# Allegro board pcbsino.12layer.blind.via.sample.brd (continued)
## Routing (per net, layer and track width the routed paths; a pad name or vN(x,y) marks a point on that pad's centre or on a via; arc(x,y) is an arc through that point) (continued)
ETH0_DVDD10: length 6.1
  INT_L3 w0.254: v3(49.22,34.07) 49.42,34.28 v2(49.93,34.28)
  SIG_L10 w0.254: v5(49.72,34.18) 49.7,34.2 49.34,34.2 v3(49.22,34.07)
  BOTTOM w0.114: 49.98,34.68 C195.1 50.11,34.33 ; 50,34.45 v5(49.72,34.18)
  BOTTOM w0.381: 50.11,34.33 49.98,34.45 49.98,34.61 ; 49.98,34.61 49.95,34.64 49.86,34.55 49.5,34.55 49.04,35.01 48.33,35.01 L15.1 ; 49.98,34.61 49.98,34.68 49.68,34.98 49.68,35.75 C194.1 ; C195.1 50,34.45
ETH0_DVDD33: length 40.9
  TOP w0.114: 43.64,35.12 44.86,35.12
  TOP w0.254: R288.2 44.96,35.21 44.86,35.12 ; R276.1 53.05,37.89 52.82,37.89 52.81,37.91 52.7,37.91 52.31,38.29 49.52,38.29 v2(49.32,38.09) ; R277.1 46.97,28.58 R284.2 ; U17.29 47.25,32.09 47,31.84 C181.1 v2(47.01,31.61) 47.72,31.61 47.8,31.69 U17.30 ; 43.64,35.12 v2(43.35,35.12) 43.35,35.45 43.32,35.48 R279.2
  INT_L3 w0.254: 46.98,31.59 v2(47.01,31.61) ; 46.98,31.59 46.98,33.09 48.07,34.18 v3(48.51,34.18) ; 46.98,31.59 46.98,31.23 46.58,30.82 46.58,29.81 v2(46.98,29.4) ; v2(43.35,35.12) 43.37,35.09 v3(43.37,34.63) 43.37,34.58 43.4,34.56 v2(43.4,33.87) ; v3(49.18,37.71) 49.19,37.71 49.19,37.73 49.22,37.76 49.22,37.99 v2(49.32,38.09)
  SIG_L10 w0.254: v5(43.37,34.15) v3(43.37,34.63) ; v5(48.63,37.94) 48.84,37.73 49.16,37.73 v3(49.18,37.71)
  SIG_L10 w0.381: v3(48.51,34.18) 48.56,34.23 48.56,35.53 v4(48.72,35.7)
  GND_L11 w0.381: v5(48.87,36.07) v4(48.72,35.7)
  BOTTOM w0.254: v5(48.63,37.94) 48.48,37.78 C183.1 ; 46.24,36.5 45.89,36.84 44.34,36.84 43.37,35.88 v5(43.37,34.15) 43.25,34.15 42.54,33.44 42.54,31.13 41.9,30.49 41.11,30.49 R259.2
  BOTTOM w0.381: v5(48.87,36.07) 47.35,36.07 47.08,36.34 C182.1 46.24,36.39 C183.1 46.19,37.83 L11.1
ETH0_INTN: length 51.7
  TOP w0.114: U17.34 47.18,30.09 R277.2
  INT_L3 w0.091: v3(48.53,29.6) 47.69,29.6 v2(47.03,30.26) ; v3(31.69,19.32) 31.49,19.11 v2(31.49,18.76)
  SIG_L10 w0.091: v3(48.53,29.6) 48.51,29.58 48.51,28.18 50.51,26.18 50.51,20.08 50.97,19.62 50.97,19.2 50.76,18.99 50.54,18.99 48.3,16.75 46.68,16.75 46.14,16.22 46.14,13.96 45.59,13.4 45.59,10.42 46.5,9.51 46.5,9.03 45.9,8.44 39.05,8.44 36.2,11.29 35.23,11.29 34.05,12.47 33.58,12.47 32.02,14.03 32.02,16.58 31.69,16.91 v3(31.69,19.32)
ETH0_LED0/PHYAD0: length 4.1
  TOP w0.114: R283.2 47.49,27.12 R284.1 47,27.62 47.44,28.06 47.44,29.3 47.83,29.69 U17.35
ETH0_RESETN: length 21.4
  TOP w0.114: v2(39.94,31.23) 39.49,30.78 39.47,30.78 U6.U3 ; v2(41.85,39.56) 42.16,39.56 42.21,39.51 46.96,39.51 49.64,42.2 R275.2 50.08,42.59 U18.1
  INT_L3 w0.091: v2(41.85,39.56) 41.57,39.84 v3(41.44,39.84) ; v2(39.94,31.23) 40.02,31.31 v3(40.58,31.31)
  SIG_L10 w0.091: v3(40.58,31.31) 40.54,31.35 40.54,36.09 41.09,36.65 41.09,39.57 41.36,39.84 v3(41.44,39.84)
ETH0_RSET: length 1.7
  TOP w0.114: U17.48 53.53,28.09 53.84,27.78 54.33,27.78 R272.2
ETH0_VDD10: length 12.7
  SIG_L10 w0.381: v5(50.08,29.22) 49.5,29.81 49.5,32.4 48.86,33.03 v5(48.86,33.26)
  BOTTOM w0.114: C186.1 49.88,29.43 v5(50.08,29.22)
  BOTTOM w0.254: v5(50.08,29.22) 50.12,29.18 C187.1
  BOTTOM w0.381: v5(48.86,33.26) 48.43,33.69 L15.2 ; 50.1,29.21 48.78,29.21 48.61,29.38 48.61,28.11 L14.2 47.48,28.73 L13.2
ETH0_VDDREG33: length 5.6
  TOP w0.114: v2(48.07,31.29) U17.31
  INT_L3 w0.254: v3(48.68,31.59) 48.37,31.59 v2(48.07,31.29)
  SIG_L10 w0.254: v3(48.68,31.59) 48.63,31.59 47.91,32.31 v5(47.86,32.31)
  BOTTOM w0.254: C184.1 47.78,32.37 47.79,32.37 v5(47.86,32.31)
  BOTTOM w0.381: C184.1 46.93,32.4 C185.1 46.7,32.97 L12.1
ETH0_XTAL_IN: length 5.5
  TOP w0.114: Y4.3 51.06,23.92 51.96,24.82 51.96,26.61 51.58,26.98 C188.1 52.33,27.82 U17.45
ETH0_XTAL_OUT: length 4.9
  TOP w0.114: Y4.1 53.09,25.52 52.54,24.98 52.38,24.98 52.26,25.09 52.26,26.83 C191.1 52.53,27.41 52.73,27.6 U17.46
ETH1_AND_RESETN: length 4.3
  TOP w0.114: U20.4 53.76,18.89 53.94,18.71 53.94,17.7 R305.2 53.78,17.54 51.96,17.54 51.69,17.27 U19.13
ETH1_AVDD10: length 16.8
  TOP w0.114: 51.29,10.74 51.3,10.73 v2(51.3,10.71)
  TOP w0.254: v2(51.3,10.71) 51.29,10.72 U19.47 ; U19.9 v2(53.1,14.96) ; U19.4 v2(53.15,12.96)
  INT_L3 w0.254: v2(53.1,14.96) 52.71,14.57 v3(52.52,14.57) 52.47,14.52 52.47,13.64 v2(53.15,12.96) ; v2(51.3,10.71) 51.33,10.68 51.33,10.3 v3(51.25,10.22)
  SIG_L10 w0.254: v5(51.73,10.27) 51.71,10.25 51.27,10.25 v3(51.25,10.22) ; v5(52.65,13.86) 52.52,13.98 v3(52.52,14.57)
  BOTTOM w0.381: C211.1 52.64,12.98 C210.1 52.64,12.65 51.67,11.69 C212.1 51.67,10.33 v5(51.73,10.27) 51.66,10.2 51.66,9.23 50.91,8.49 C213.1 47.63,8.13 L20.1
ETH1_AVDD33: length 14.3
  TOP w0.254: v2(53.04,11.7) 52.98,11.76 U19.1 ; U19.12 v2(53.12,16.16)
  INT_L3 w0.254: v2(53.12,16.16) 52.39,15.43 v3(52.39,15.28)
  INT_L3 w0.381: v2(53.04,11.7) 53.1,11.63 v3(53.1,11.27)
  SIG_L10 w0.254: v5(52.39,15.66) v3(52.39,15.28)
  SIG_L10 w0.381: v5(53.1,11.77) v3(53.1,11.27)
  BOTTOM w0.114: 53.06,11.77 v5(53.1,11.77)
  BOTTOM w0.254: v5(52.39,15.66) 52.4,15.65 52.4,15.63
  BOTTOM w0.381: L16.1 50,16.95 C200.1 50.56,17 52.4,17 52.67,16.73 C199.1 52.67,15.9 52.4,15.63 53.31,14.72 53.31,12.02 C198.1
ETH1_DVDD10: length 6.7
  TOP w0.114: C214.1 48.09,18.15 U19.22
  TOP w0.254: C214.1 48.03,18.33 49,19.29 v2(49.01,19.29)
  INT_L3 w0.254: v3(49.34,18.81) 49.01,19.14 v2(49.01,19.29)
  SIG_L10 w0.254: v3(49.34,18.81) 49.34,18.76 v5(48.35,17.77)
  BOTTOM w0.381: L21.1 48.18,18.17 C215.1
ETH1_DVDD33: length 34.2
  TOP w0.203: 44.28,8.33 44.28,8.37 R306.1 ; 44.28,8.33 R313.2 ; 44.28,8.33 v2(43.93,8.67) ; U19.29 46.08,14.56 45.61,14.08 v7(45.61,14.03) 45.73,14.16 U19.30
  TOP w0.254: R305.1 54.77,17.19 54.52,16.93 v2(52.39,16.93) ; R317.2 43.3,12.28 v2(43.32,12.26) ; R308.2 42.76,14.28 v2(42.49,14.01)
  INT_L3 w0.203: v2(43.32,12.26) 44.64,10.94 44.64,9.39 v2(43.93,8.67)
  INT_L3 w0.254: v2(43.32,12.26) 43.4,12.33 44.34,12.33 45.61,13.6 v7(45.61,14.03) 45.64,14.06 45.64,14.69 46.45,15.51 50.72,15.51 52.14,16.93 v2(52.39,16.93) ; v2(41.62,12.79) 41.85,12.79 v3(42.1,13.04) 42.49,13.42 v2(42.49,14.01)
  SIG_L10 w0.254: v7(45.61,14.03) 44.62,13.04 v3(42.1,13.04)
  BOTTOM w0.381: L17.1 44.92,16.39 C203.1 44.99,16.1 C201.1 C202.1 45.69,14.12 v7(45.61,14.03)
ETH1_INTN: length 22.2
  TOP w0.114: v2(44.26,9.77) 44.33,9.7 R306.2 45.64,10.68 45.64,12.28 45.91,12.56 U19.34
  TOP w0.12: v8(32.68,17.58) U6.A11
  INT_L3 w0.091: v2(44.26,9.77) 43.88,9.39 43.83,9.39 v3(43.81,9.36)
  SIG_L10 w0.091: v3(43.81,9.36) 41.87,9.36 37.48,13.75 33.73,13.75 32.68,14.81 32.68,16.85 32.68,16.85 v8(32.68,17.58)
ETH1_LED0/PHYAD0: length 5.5
  TOP w0.114: U19.35 46,12.16 45.89,12.04 45.89,10.04 45.66,9.81 45.66,8.65 45.44,8.43 R312.2 45.2,7.66 R313.1
ETH1_RESETN: length 25.6
  TOP w0.114: U20.1 50.9,21 R304.2
  INT_L3 w0.091: v2(50.61,20.89) 50.54,20.89 50.44,20.79 v3(50.08,20.79) ; v2(32.28,18.78) 32.61,18.45 v3(32.61,18.38)
  SIG_L10 w0.091: v3(50.08,20.79) 50.08,20.69 48.73,19.34 43.81,14.41 34.09,14.41 33.06,15.44 33.06,17.75 32.72,18.09 32.72,18.26 v3(32.61,18.38)
ETH1_RSET: length 1.7
  TOP w0.114: U19.48 51.69,10.75 52.65,9.79 R301.2
ETH1_VDD10: length 19.4
  TOP w0.381: L19.2 39.82,7.5 C206.1 38.38,7.58 C208.1 38.33,7.19 v2(38.45,7.07)
  INT_L3 w0.381: v2(38.9,7.07) v2(38.45,7.07)
  SIG_L10 w0.254: v5(45.83,7.29) 46.03,7.29 v3(46.25,7.07) 46.29,7.07 46.85,6.52 48.23,6.52 48.51,6.79 48.51,8.57 46.22,10.86 46.22,13.27 46.7,13.75 v5(46.7,15.99)
  BOTTOM w0.114: v5(45.83,7.29) L20.2
  BOTTOM w0.381: L21.2 46.72,16.01 v5(46.7,15.99)
  vias: v1(38.65,6.74) v1(38.85,7.51) v1(39.11,6.74) v2(38.65,6.74) v2(38.85,7.51) v2(39.11,6.74)
ETH1_VDDREG33: length 6.6
  INT_L3 w0.254: v3(47.29,13.25) 46.78,13.75 v2(46.25,13.75)
  SIG_L10 w0.254: v5(46.8,12.08) v5(46.8,12.43) 46.8,12.76 v3(47.29,13.25)
  BOTTOM w0.254: v5(46.8,12.43) 46.75,12.43 46.18,13
  BOTTOM w0.381: C204.1 46.18,12.19 C205.1 46.41,10.39 L18.1
ETH1_XTAL_IN: length 5.7
  TOP w0.114: Y5.3 49.95,7.73 49.95,9.08 C207.1 49.28,9.81 49.75,10.27 50.21,10.27 50.49,10.56 U19.45
ETH1_XTAL_OUT: length 4.7
  TOP w0.114: Y5.1 50.64,7.81 50.41,7.81 50.26,7.96 50.26,9.33 50.63,9.71 C209.1 50.51,9.88 50.51,10.04 50.89,10.42 U19.46
GPIO1_4: length 9.6
  TOP w0.114: U6.D15 v2(29.43,19.93) ; v2(29.61,13.91) 30.83,13.91 31.72,14.8 TP30.1
  INT_L3 w0.091: v2(29.61,13.91) 29.61,15.96 29.09,16.48 29.09,19.55 29.26,19.73 29.26,19.77 v2(29.43,19.93)
GPIO2_29: length 6.4
  TOP w0.114: U6.B17 27.86,18.37 27.86,17.29 28.47,16.68 28.47,14.96 28.82,14.62 30.28,14.62 TP32.1
GPIO5_5: length 9.1
  TOP w0.114: U6.J11 v2(33.52,23.91)
  INT_L3 w0.091: v2(34.55,16.16) 34.33,16.38 34.33,17.31 34.66,17.64 34.66,19.24 33.84,20.06 33.84,23.59 v2(33.52,23.91)
GPIO5_6: length 8.1
  TOP w0.114: v2(32.55,15.41) 32.56,15.35 33.26,14.75 TP29.1 ; U6.E12 v2(32.61,20.69)
  INT_L3 w0.091: v2(32.61,20.69) 32.47,20.69 31.19,19.4 31.19,18.5 32.06,17.63 32.06,17.32 32.52,16.85 32.52,15.49 32.55,15.46 v2(32.55,15.41)
GPIO6_7: length 3.7
  TOP w0.12: TP31.1 30.11,16.02 28.66,17.47 28.66,18.36 U6.B16
I2C1_SCL: length 112.4
  TOP w0.114: U3.L1 27.27,60.54 v2(27.27,60.57)
  TOP w0.12: U6.C20 26.23,19.93 26.23,19.95 v8(26.25,19.98)
  INT_L3 w0.091: v3(26.76,60.85) 26.99,60.85 v2(27.27,60.57)
  SIG_L5 w0.091: v3(26.76,60.85) 26.64,60.97 10.33,60.97 1.36,52.01 1.36,15.48 2.38,14.47 2.38,7.51 3.64,6.25 16.01,6.25 18.28,8.52 18.28,17.41 19.12,18.25 24.53,18.25 v8(26.25,19.98)
  BOTTOM w0.114: R245.2 26.13,19.05 26.23,19.15 26.23,19.95 v8(26.25,19.98)
I2C1_SDA: length 109.3
  TOP w0.114: v2(27.17,59.83) 27.17,59.78 U3.L2
  TOP w0.12: v8(24.67,19.17) U6.C21
  INT_L3 w0.091: v2(27.17,59.83) 27.17,59.86 26.86,60.16 v3(26.86,60.21)
  SIG_L5 w0.091: v3(26.86,60.21) 26.81,60.21 26.31,60.72 10.38,60.72 1.59,51.93 1.59,15.56 2.6,14.56 2.6,7.6 3.71,6.49 15.84,6.49 18.05,8.7 18.05,17.51 19.02,18.48 24.3,18.48 24.67,18.85 v8(24.67,19.17)
  BOTTOM w0.114: R244.2 25.16,18.68 v8(24.67,19.17)
I2C3_SCL: length 5.6
  TOP w0.114: U6.D14 v2(30.65,20.36) ; TP34.1 v2(32.1,16.8)
  INT_L3 w0.091: v2(30.65,20.36) 30.65,19.77 30.97,19.45 30.97,18.4 31.82,17.56 31.82,17.08 v2(32.1,16.8)
I2C3_SDA: length 4
  TOP w0.12: TP35.1 31.54,16.37 31.54,16.88 31.08,17.34 31.08,19.16 U6.C14
I2C4_SCL: length 137.9
  TOP w0.114: v2(27.04,58.28) 27.02,58.3 27.02,58.34 U3.M3
  TOP w0.12: v8(31.07,23.97) U6.J14
  INT_L3 w0.091: v3(27.38,57.94) v2(27.04,58.28)
  SIG_L10 w0.091: v8(31.07,23.97) 30.27,23.17 30.27,15.41 30.44,15.23 30.44,13.88 33.97,10.35 35.27,10.35 v5(35.35,10.27) ; v3(27.38,57.94) 27.29,57.94 27.02,57.67 24.73,57.67 23.89,58.51 7.64,58.51 1.34,52.21 1.34,14.67 2.16,13.85 2.16,7.45 3.6,6.01 16.25,6.01 17.05,6.8 24.48,6.8 26.83,4.46 30.24,4.46 v5(30.8,3.9)
  BOTTOM w0.114: 30.81,3.91 30.64,3.91 30.32,4.23 30.32,5.78 31.84,7.3 31.84,9.23 32.81,10.2 35.3,10.2 35.35,10.25 ; 30.81,3.91 U16.6 34.12,3.91 R247.1 ; 30.81,3.91 v5(30.8,3.9) ; 35.35,10.25 v5(35.35,10.27) ; 35.35,10.25 35.57,10.48 U13.4
I2C4_SDA: length 134
  TOP w0.114: U3.H8 30.22,54.9 v2(30.22,54.98)
  TOP w0.12: v2(30.42,16.83) 30.27,16.98 30.27,18.37 U6.B14
  INT_L3 w0.091: v3(30.67,16.29) 30.42,16.55 v2(30.42,16.83) ; v2(30.22,54.98) v3(29.71,54.98)
  SIG_L10 w0.091: v5(36.21,10.27) 36.19,10.3 36.19,10.38 35.88,10.68 33.95,10.68 30.66,13.97 30.66,15.75 30.67,15.76 v3(30.67,16.29) ; v5(30.85,5.09) 30.5,4.74 26.86,4.74 24.57,7.02 16.88,7.02 16.2,6.34 3.58,6.34 2.38,7.54 2.38,13.94 2.25,14.07 1.56,14.76 1.56,52.1 7.69,58.23 23.61,58.23 24.42,57.42 27.78,57.42 29.15,56.05 29.15,55.54 v3(29.71,54.98)
  BOTTOM w0.114: R246.1 34.25,5.18 U16.5 30.99,5.18 30.78,5.4 30.78,5.73 32.17,7.13 32.17,9.22 32.9,9.94 35.88,9.94 v5(36.21,10.27) 36.37,10.44 U13.5
LDO_VRTC: length 38.4
  TOP w0.254: TP15.1 43.04,55.13 41.01,55.13 R49.1 ; U6.AB13 31.47,34.83 v8(31.09,35.2) ; v2(38.07,4.69) 38.07,4.59 37.81,4.33 C155.1 37.24,4.77 U14.6
  TOP w0.381: R49.1 40.79,55.31 38.61,55.31 38.14,54.84 C36.2 35.59,54.57 U3.A8 ; R20.2 43.99,55.94 TP15.1
  INT_L3 w0.254: v3(33.34,54.78) 33.34,54.74 33.6,54.49 34.48,54.49 34.74,54.75 37.86,54.75 v2(37.99,54.62) 38.16,54.45 38.64,54.45 38.81,54.62 v7(38.83,54.62) ; v3(37.61,5.4) 38.07,4.94 v2(38.07,4.69)
  SIG_L10 w0.254: v5(29.81,56.38) 32.17,56.38 33.34,55.21 v3(33.34,54.78) ; v5(28.15,57.51) 28.34,57.7 30.04,57.7 31.13,58.79 v5(31.13,58.92)
  BOTTOM w0.114: C65.1 32.03,37.74 30.68,36.39 30.68,35.61 v8(31.09,35.2)
  BOTTOM w0.254: R32.2 29.63,56.38 v5(29.81,56.38) ; R32.2 29.58,56.44 29.15,56.86 28.61,56.86 R30.2 ; R32.2 29.51,56.26 R41.1 R28.1
  vias: v4(32.02,40.58) v4(32,40.2) v5(32.02,40.58) v5(32,40.2)
LJCB_CLK_N: length 3.3
  TOP w0.102: C175.2 29.59,41.93 29.59,41.58 R252.1 29.83,40.93 29.74,40.84 29.52,40.84 29.43,40.75 29.43,40.63 29.52,40.54 29.74,40.54 29.83,40.45 29.83,39.61 U6.AH15
LJCB_CLK_P: length 3.8
  TOP w0.102: C176.2 28.88,42.04 R252.2 29.15,41.07 29.15,40.27 29.48,39.94 29.48,39.16 U6.AG15
MDIO_DATA: length 41.7
  TOP w0.114: v2(52.54,35.24) 52.72,35.07 52.72,34.45 U17.15 ; U19.15 v2(50.89,17.89)
  TOP w0.12: v8(39.07,31.17) U6.U4
  INT_L3 w0.091: v2(52.54,35.24) 52.54,35.14 49.64,32.24 49.64,26.96 49.28,26.6 49.28,26.59 49.22,26.53 49.22,19.6 49.67,19.14 49.87,19.14 v3(50.61,18.4) 50.61,18.38 50.89,18.1 v2(50.89,17.89)
  SIG_L8 w0.091: v8(39.07,31.17) 39.73,31.17 41.05,29.85 41.05,29.28 41.89,28.45 41.89,28.19 42.01,28.06 44.29,25.79 44.29,24.52 45.98,22.84 45.98,22.17 46.54,21.61 47.2,21.61 50.41,18.4 v3(50.61,18.4)
  BOTTOM w0.114: R259.1 39.3,30.89 39.3,30.94 v8(39.07,31.17)
MDIO_MCLK: length 41.2
  TOP w0.114: v2(52.8,35.65) 53.15,35.29 53.15,34.47 U17.14 ; U19.14 v2(51.29,17.62)
  TOP w0.12: v2(41.83,31.48) 41.74,31.57 U6.V1
  INT_L3 w0.091: v2(51.29,17.62) 51.29,18.58 v3(51.19,18.68) 51.19,19.05 49.5,20.74 49.5,26.51 49.86,26.87 49.86,32.07 52.87,35.09 52.87,35.57 v2(52.8,35.65) ; v2(41.83,31.48) 41.83,31.13 v3(41.67,30.98)
  SIG_L8 w0.091: v3(41.67,30.98) 41.67,30.92 41.27,30.52 41.27,29.38 42.1,28.54 42.1,28.28 44.54,25.84 44.54,24.65 46.19,23 46.19,22.26 46.63,21.83 47.36,21.83 49.14,20.05 50.03,20.05 51.19,18.9 v3(51.19,18.68)
Net_455: length 0.6
  TOP w0.12: v8(7.53,38.21) 7.93,37.81
Net_886: length 0.6
  TOP w0.12: v8(38.27,29.58) 37.87,29.17
Net_908:
  vias: v1(57.65,17.77) v2(57.65,17.77)
OSC0_XI: length 7.2
  TOP w0.12: v8(29.47,37.57) U6.AE15
  BOTTOM w0.114: Y2.1 30.02,42.01 29.91,42.13 29.16,42.13 29.05,42.01 29.05,41.11 29.33,40.83 29.62,40.83 C58.1 30.05,40.05 29.47,39.47 v8(29.47,37.57)
OSC0_XO: length 7.9
  TOP w0.12: v8(29.47,36.77) U6.AD15
  BOTTOM w0.114: Y2.3 27.96,43.34 28.74,42.56 28.74,40.54 C57.1 29.02,40.26 29.02,37.38 29.47,36.93 v8(29.47,36.77)
OSC1_XI: length 12.2
  TOP w0.12: v8(29.47,35.97) U6.AC15
  SIG_L10 w0.091: v5(34.66,40.04) 34.65,40.04 33,40.04 31.7,38.73 31.7,37.23 30.44,35.97 v8(29.47,35.97)
  BOTTOM w0.114: Y3.1 35.09,42.33 35.09,40.98 34.66,40.54 R62.1 v5(34.66,40.04)
OSC1_XO: length 11
  TOP w0.12: v8(31.08,36) 31.08,35.96 U6.AC13
  SIG_L10 w0.091: v8(31.08,36) 31.92,36.84 31.92,38.48 33.1,39.66 35.02,39.66 v5(35.3,39.94)
  BOTTOM w0.114: Y3.3 35.78,42.25 35.48,42.25 35.37,42.15 35.37,40.98 35.66,40.7 C60.1 35.66,40.3 v5(35.3,39.94)
PCIE_TX0_N: length 3.7
  TOP w0.102: U6.AG14 30.67,38.94 30.25,39.37 30.25,39.64 30.24,39.64 30.24,40.2 30.45,40.4 30.45,41.52 30.64,41.72 C169.1
PCIE_TX0_P: length 3.2
  TOP w0.102: C168.1 31.39,42.05 31.39,41.72 31.28,41.62 30.9,41.62 30.7,41.42 30.7,40.3 30.5,40.09 30.5,39.74 U6.AH14
PCIE_TX1_N: length 3.1
  TOP w0.102: U6.AG12 32.68,39.19 32.68,41.22 C174.1
PCIE_TX1_P: length 2.4
  TOP w0.102: C172.1 32.43,41.35 32.43,41.15 32.28,41 32.28,40.85 32.43,40.7 32.43,40.54 32.28,40.39 32.28,40.24 32.43,40.09 32.43,39.73 U6.AH12
PMIC_INT: length 57.7
  TOP w0.114: R58.1 23.46,61.15 v2(23.51,61.1) 23.56,61.15 27.41,61.15 U3.K1
  TOP w0.12: v8(27.87,36.77) U6.AD17
  INT_L3 w0.091: v2(29.05,15.18) 29.05,15.61 28.87,15.79 28.87,19.64 29.04,19.82 29.04,22.62 28.6,23.06 28.6,24.96 v3(28.56,25) ; v2(23.51,61.1) 23.74,60.87 v3(23.74,60.19)
  SIG_L5 w0.091: v3(28.56,25) 28.74,25 29.05,25.32 29.05,32.1 29.76,32.8 29.76,34.21 29.56,34.41 29.5,34.41 29.39,34.52 29.05,34.52 29.04,34.51 28.71,34.51 28.7,34.52 28.5,34.52 28.13,34.89 27.71,34.89 27.48,35.13 27.48,36.16 27.87,36.55 v8(27.87,36.77) 28.85,37.75 28.85,43.98 26.66,46.16 26.66,47.66 23.31,51.02 23.31,59.75 v3(23.74,60.19)
PMIC_OFF: length 68
  TOP w0.12: v8(33.47,33.57) U6.Y11
  SIG_L5 w0.091: v8(33.47,33.57) 33.47,33.82 32.94,34.35 32.94,35.74 33.02,35.83 33.02,39.85 32.05,40.82 32.05,41.45 32.81,42.2 41.65,42.2 43.15,43.7 43.15,46.29 44.72,47.87 44.72,49.09 45.84,50.2 46.14,50.2 48.15,52.21 49.12,52.21 51.78,54.88 51.78,61.43 52.16,61.81 v3(52.16,62.04)
  SIG_L10 w0.091: v5(33.59,58.11) 33.59,58.92 37.35,62.67 44.64,62.67 45.82,61.49 50.93,61.49 51.48,62.04 v3(52.16,62.04)
  BOTTOM w0.114: R53.2 34.82,33.98 33.87,33.98 v8(33.47,33.57) ; R19.1 33.12,57.86 33.38,58.11 v5(33.59,58.11)
PMIC_RESET_IN: length 22.4
  TOP w0.114: U1.1 44.93,54.96 44.59,54.62 44.59,53.66 v2(44.47,53.53) ; U3.K9 28.34,53.81 v7(27.98,53.45)
  INT_L3 w0.091: v7(27.98,53.45) 29.2,53.45 29.61,53.05 31.46,53.05 32.35,52.16 32.94,52.16 33.03,52.24 33.9,52.24 34.55,51.59 43.09,51.59 44.47,52.97 v2(44.47,53.53)
  BOTTOM w0.114: v7(27.98,53.45) 27.98,53.59 R28.2
PMIC_RESET_OUT: length 133.3
  TOP w0.114: U3.G6 v2(31.1,56.59)
  INT_L3 w0.091: v2(31.1,56.59) 31.77,56.59 33.47,58.28 33.47,58.92 34,59.45 34.88,59.45 34.93,59.4 35.26,59.4 35.43,59.4 36.19,60.16 37.05,60.16 39.08,62.19 v3(46.6,62.19)
  SIG_L5 w0.091: v3(46.6,62.19) 50.77,62.19 52.6,64.02 54.42,64.02 55.98,65.58 57.74,65.58 59.46,63.86 59.46,30.61 55.57,26.72 55.57,22.45 56.31,21.71 56.31,20.53 57.52,19.32 57.52,10.78 56.66,9.92 56.66,6.63 55.05,5.03 51.44,5.03 51.36,5.11 47.2,5.11 45.69,3.59 38.67,3.59 36.45,2.22 v3(20.95,2.22)
  SIG_L10 w0.091: v5(20.57,1.77) 20.57,1.84 v3(20.95,2.22)
  BOTTOM w0.114: U7.2 20.68,1.92 R65.2
PMIC_SMPS_POWERGOOD: length 20.8
  TOP w0.114: Q3.G 47.22,57.61 46.93,57.9 46.01,57.9 R21.1 R20.1 45.91,56.35 v2(45.89,56.32)
  INT_L3 w0.091: v2(45.89,56.32) 45.84,56.32 45.64,56.12 40.99,56.12 39.79,54.93 39.11,54.93 38.93,55.11 34.82,55.11 34.49,55.43 34.04,55.43 33.8,55.2 33.06,55.2 32.82,55.44 31.32,55.44 31.3,55.42 29.17,55.42 v2(29.15,55.44)
PMIC_VBUS_DET: length 18.6
  TOP w0.114: R33.2 45.34,49.41 U4.4
  TOP w0.12: v8(40.67,36.77) U6.AD2
  INT_L3 w0.091: v3(46.93,48.7) 46.58,48.7 v2(45.81,49.47)
  SIG_L5 w0.091: v8(40.67,36.77) 41.12,37.22 41.98,37.22 45.04,40.29 45.04,42.45 45.04,45.03 46.65,46.64 46.65,48.43 v3(46.93,48.7)
PORZ: length 118.8
  TOP w0.114: v2(52.07,44.86) 52.07,41.94 51.78,41.64 U18.2 ; v2(51.53,19.77) 51.46,19.84 U20.2 R67.2
  TOP w0.12: v8(31.07,38.37) U6.AF14 ; v8(23.87,21.57) U6.F22
  INT_L3 w0.091: v2(28.27,34.77) 28.02,34.77 v3(27.7,34.46) ; v2(51.53,19.77) 51.78,19.52 51.78,19.03 51.76,19.01 51.76,18.76 51.78,18.74 51.78,17.46 50.23,15.91 46.17,15.91 45.21,14.95 45.21,14.01 44.87,13.68 44.14,13.68 42.64,12.18 40.63,12.18 40.17,11.73 40.17,9.81 36.5,6.13 25.37,6.13 v3(24.91,5.68) ; v2(52.07,44.86) v3(51.73,45.2)
  SIG_L5 w0.091: v8(31.07,38.37) 31.07,42.01 32.12,43.07 41.11,43.07 42.41,44.37 42.41,47.06 v3(42.61,47.26) ; v3(27.7,34.46) 28.29,33.87 28.29,25.41 26.45,23.56 26.13,23.56 25.89,23.33 25.89,23.07 25.62,22.8 25.14,22.8 23.91,21.57 v8(23.87,21.57)
  SIG_L8 w0.091: v3(51.73,45.2) 50.51,46.42 46.12,46.42 45.43,47.1 42.77,47.1 v3(42.61,47.26)
  SIG_L10 w0.091: v3(24.91,5.68) 24.58,6.01 20.51,6.01 v5(20.31,5.8) ; v5(22.47,15.38) 22.46,15.39 22.46,15.6 24.24,17.38 24.24,21 23.87,21.37 v8(23.87,21.57)
  SIG_L10 w0.094: v8(31.07,38.37) 31.04,38.37 29.84,37.17 29.34,37.17 29.07,36.91 29.07,36.51 28.76,36.2 28.76,35.57 27.7,34.52 v3(27.7,34.46)
  BOTTOM w0.114: v5(22.47,15.38) 22.12,15.38 ; v5(20.31,5.8) 20.31,5.81 U7.4 19.73,6.99 C64.1 R66.1
  BOTTOM w0.12: 22.12,15.38 20.17,13.43 20.17,10.26 19.78,9.87 19.78,7.95 19.93,7.8 19.93,7.78 19.97,7.75 19.99,7.75 R66.1
QSPI_FLASH_QSPI1_CS0: length 3.3
  TOP w0.12: U6.P2 40.68,27.96 43.21,27.96 R188.1
QSPI_FLASH_QSPI1_D0: length 2.4
  TOP w0.114: R179.1 42.74,31.1 42.46,30.82 41.12,30.82 U6.U1
QSPI_FLASH_QSPI1_D1: length 4.4
  TOP w0.114: U6.P3 39.73,28.11 39.73,28.09 v2(39.82,28) ; v2(42.59,27.6) 43.14,27.04 R180.1
  INT_L3 w0.091: v2(39.82,28) 42.18,28 v2(42.59,27.6)
QSPI_FLASH_QSPI1_D2: length 3.6
  TOP w0.12: R178.1 42.79,31.89 42.08,31.18 40.67,31.18 U6.U2
QSPI_FLASH_QSPI1_D3: length 3.3
  TOP w0.12: R177.1 43.3,30.38 40.67,30.38 U6.T2
QSPI_FLASH_QSPI1_RTCLK: length 4.1
  TOP w0.114: R176.1 43.28,29.56 39.77,29.56 39.47,29.25 U6.R3
QSPI_FLASH_QSPI1_SCLK: length 3.2
  TOP w0.114: R181.1 43.24,28.79 40.68,28.79 40.3,29.17 U6.R2
R__QSPI_FLASH_QSPI1_RTCLK: length 0.9
  TOP w0.114: R176.2 45.12,29.53 R187.2
R__QSPI_FLASH_QSPI1_SCLK: length 26.1
  TOP w0.114: R187.1 44.97,28.73 R181.2
  INT_L3 w0.091: v3(41.1,20.46) 41.15,20.41 41.19,20.41 41.32,20.28 44.09,20.28 45.61,21.81 45.61,26.43 45.25,26.78 45.25,28.44 v2(45.18,28.51)
  SIG_L10 w0.091: v3(41.1,20.46) 41.06,20.46 40.81,20.21 v5(40.78,20.21)
  BOTTOM w0.114: v5(40.78,20.21) 40.48,19.9 40.48,18.63 39.69,17.84 39.69,16.42 39.98,16.14 39.98,10.84 38.17,9.04 R186.1
R_EMAC[0]_RXC: length 2.6
  TOP w0.12: v8(38.27,31.17) U6.U5
  BOTTOM w0.114: v8(38.27,31.17) 38.67,31.58 39.4,31.58 R260.1
R_EMAC[0]_RXCTL: length 2.3
  TOP w0.12: v8(38.27,31.97) U6.V5
  BOTTOM w0.114: v8(38.27,31.97) 38.33,31.92 39.88,31.92 R266.1
R_EMAC[0]_RXD0: length 8.8
  TOP w0.114: R267.1 43.32,36.71 43.19,36.83 43.02,36.83 42.92,36.93 42.83,36.93 42.71,36.81 42.71,36.31 42.89,36.14 42.89,35.94 42.74,35.79 42.74,35.6 42.89,35.45 42.89,35.26 42.74,35.11 42.74,34.92 42.89,34.76 42.89,34.57 42.66,34.34 42.66,33.72 42.54,33.59 42.26,33.59 42.16,33.69 42.16,34 42.05,34.1 41.91,34.1 41.81,34 41.81,33.69 41.71,33.59 41.23,33.59 41.23,33.59 40.94,33.59 40.68,33.33 40.68,32.49 40.57,32.37 U6.W2
R_EMAC[0]_RXD1: length 9
  TOP w0.114: U6.Y2 40.27,33.36 40.68,33.77 40.68,34.15 40.91,34.38 42.03,34.38 42.46,34.81 42.46,37.71 43.09,38.34 43.69,38.34 43.86,38.18 43.86,37.79 43.68,37.61 43.67,37.61 43.32,37.26 R261.1
R_EMAC[0]_RXD2: length 11.2
  TOP w0.114: U6.V3 39.87,31.97 v2(39.87,31.99) ; R262.1 44.17,38.7 43.11,38.7 42.21,37.8 42.21,34.99 v2(41.9,34.68)
  INT_L3 w0.091: v2(39.87,31.99) 40.17,32.29 40.28,32.29 40.45,32.12 40.56,32.12 40.64,32.2 40.64,32.32 40.47,32.48 40.47,32.6 40.55,32.68 40.67,32.68 40.83,32.51 40.95,32.51 41.03,32.59 41.03,32.7 40.86,32.87 40.86,32.98 41.01,33.13 41.01,33.24 41.01,33.24 41.01,33.36 41.95,34.3 41.95,34.63 v2(41.9,34.68)
R_EMAC[0]_RXD3: length 13.1
  TOP w0.114: v2(41.77,35.07) 41.95,35.24 41.95,37.88 43.05,38.98 46.13,38.98 46.24,38.86 46.24,38.86 R263.1 ; U6.V4 v2(39.06,31.96)
  INT_L3 w0.091: v2(41.77,35.07) 41.6,34.89 41.6,34.28 39.28,31.96 v2(39.06,31.96)
R_EMAC[0]_TXC: length 2.6
  TOP w0.114: R268.2 48.85,36.34 50.33,34.87 U17.21
R_EMAC[0]_TXCTL: length 2.4
  TOP w0.114: R264.2 50.73,35.21 U17.20
R_EMAC[0]_TXD0: length 2.2
  TOP w0.114: R265.2 51.13,35.6 U17.19
R_EMAC[0]_TXD1: length 2
  TOP w0.114: U17.18 51.53,35.99 R269.2
R_EMAC[0]_TXD2: length 1.9
  TOP w0.114: U17.17 51.93,36.28 R270.2
R_EMAC[0]_TXD3: length 2.1
  TOP w0.114: U17.16 52.33,35.85 R271.2
R_EMAC[1]_RXC: length 9.1
  TOP w0.114: v2(39.44,12.87) 39.44,12.92 R290.1 ; U6.C5 38.28,19.16 v2(39.9,19.16)
  INT_L3 w0.091: v2(39.9,19.16) 39.9,19.11 39.9,16.71 39.9,16.7 39.9,14.51 40.12,14.29 40.12,13.5 39.49,12.87 v2(39.44,12.87)
R_EMAC[1]_RXCTL: length 12.8
  TOP w0.12: v2(40.4,16.67) 39.52,17.55 39.52,17.92 U6.A3
  INT_L3 w0.091: v2(41.44,13.35) 41.44,13.2 41.19,12.94 40.49,12.94 40.4,13.03 40.4,13.18 40.48,13.26 40.93,13.26 41.01,13.34 41.01,13.45 40.93,13.54 40.48,13.54 40.4,13.62 40.4,13.8 40.48,13.88 41.39,13.88 41.47,13.96 41.47,14.08 41.39,14.16 40.48,14.16 40.4,14.24 40.4,14.35 40.48,14.43 41.39,14.43 41.47,14.51 41.47,14.63 41.39,14.71 40.48,14.71 40.4,14.79 40.4,14.93 40.48,15.01 40.73,15.01 40.81,15.09 40.81,15.2 40.73,15.28 40.48,15.28 40.4,15.36 40.4,15.48 40.48,15.56 40.73,15.56 40.81,15.64 40.81,15.75 40.73,15.83 40.48,15.83 40.4,15.91 v2(40.4,16.67)
R_EMAC[1]_RXD0: length 14.1
  TOP w0.114: U6.A4 38.67,17.06 38.79,16.95 38.93,16.95 39.01,17.03 39.16,17.03 39.26,16.93 39.26,16.79 39.17,16.7 39.17,16.56 39.27,16.46 39.41,16.46 39.5,16.55 39.64,16.55 39.74,16.45 39.74,16.31 39.65,16.22 39.65,16.08 39.79,15.94 39.79,14.82 40.33,14.29 42.13,14.29 42.36,14.52 42.36,15.07 42.18,15.25 41.67,15.25 41.57,15.35 41.57,16.48 41.46,16.6 41.25,16.6 41.14,16.71 41.14,16.97 41.33,17.16 41.75,17.16 41.88,17.03 41.88,16.02 42,15.89 42.78,15.89 42.89,15.77 42.89,15.52 42.78,15.41 R291.1
R_EMAC[1]_RXD1: length 15.2
  TOP w0.114: v2(42.26,16.24) 42.54,16.24 42.61,16.31 R292.1 ; U6.B5 37.99,18.77 38.25,18.51 38.25,17.14 39.49,15.9 39.49,14.77 40.28,13.98 v2(41.93,13.98)
  INT_L3 w0.091: v2(42.26,16.24) 42.26,16.22 42.52,15.96 42.52,14.98 42.6,14.9 42.71,14.9 42.79,14.98 42.79,15.55 42.87,15.63 42.99,15.63 43.07,15.55 43.07,14.98 43.15,14.9 43.26,14.9 43.34,14.98 43.34,15.4 43.42,15.48 43.61,15.48 43.71,15.39 43.71,14.64 43.37,14.31 42.25,14.31 v2(41.93,13.98)
R_EMAC[1]_RXD2: length 3.4
  TOP w0.114: R293.1 40.3,16.35 39.08,17.57 39.08,18.36
  TOP w0.12: 39.08,18.36 U6.B4
R_EMAC[1]_RXD3: length 3.4
  TOP w0.114: R294.1 40.81,16.31 40.81,16.74 39.85,17.7 39.85,18.35 39.47,18.73 U6.B3
R_EMAC[1]_TXC: length 12.6
  TOP w0.114: R297.2 44.15,20.08 44.41,20.08 44.67,19.82 v2(44.67,19.01) ; U19.21 48.49,17.5 48.59,17.6 48.63,17.6 48.73,17.7 48.73,17.84 48.63,17.94 48.59,17.94 48.49,18.04 48.49,18.21 48.6,18.32 48.82,18.32 v2(48.96,18.17)
  INT_L3 w0.091: v2(48.96,18.17) 48.82,18.32 48.71,18.32 48.61,18.43 48.39,18.43 48.31,18.51 48.31,18.68 48.23,18.76 48.12,18.76 48.04,18.68 48.04,18.51 47.95,18.43 47.84,18.43 47.76,18.51 47.76,18.68 47.68,18.76 47.57,18.76 47.49,18.68 47.49,18.51 47.41,18.43 47.29,18.43 47.21,18.51 47.21,18.68 47.13,18.76 47.02,18.76 46.94,18.68 46.94,18.51 46.86,18.43 46.74,18.43 46.66,18.51 46.66,18.68 46.58,18.76 46.47,18.76 46.39,18.68 46.39,18.51 46.31,18.43 46.2,18.43 46.11,18.51 46.11,18.68 46.03,18.76 45.92,18.76 45.84,18.68 45.84,18.51 45.76,18.43 45.65,18.43 45.57,18.51 45.57,19.01 45.49,19.09 45.37,19.09 45.29,19.01 45.29,18.51 45.21,18.43 44.8,18.43 44.67,18.56 v2(44.67,19.01)
R_EMAC[1]_TXCTL: length 14.9
  TOP w0.114: v2(48.89,16.73) 48.89,16.9 U19.20
  INT_L3 w0.091: v2(48.89,16.73) 48.06,16.73 47.98,16.81 47.98,17 47.9,17.08 47.78,17.08 47.7,17 47.7,16.81 47.62,16.73 47.51,16.73 47.43,16.81 47.43,17 47.35,17.08 47.23,17.08 47.15,17 47.15,16.81 47.07,16.73 46.96,16.73 46.88,16.81 46.88,17 46.8,17.08 46.69,17.08 46.61,17 46.61,16.81 46.53,16.73 46.41,16.73 46.33,16.81 46.33,17 46.25,17.08 46.14,17.08 46.06,17 46.06,16.81 45.98,16.73 45.86,16.73 45.78,16.81 45.78,17 45.7,17.08 45.59,17.08 45.51,17 45.51,16.81 45.43,16.73 45.31,16.73 45.23,16.81 45.23,17 45.15,17.08 45.04,17.08 44.96,17 44.96,16.81 44.88,16.73 44.77,16.73 44.69,16.81 44.69,17 44.6,17.08 44.49,17.08 44.41,17 44.41,16.81 44.33,16.73 43.91,16.73 43.83,16.81 43.83,17.38 43.75,17.46 43.63,17.46 43.55,17.38 43.55,16.81 43.47,16.73 43.36,16.73 43.28,16.81 43.28,17.38 43.2,17.46 43.08,17.46 43,17.38 43,16.81 42.92,16.73 42.74,16.73 42.54,16.93 42.54,17.7 42.63,17.79 43.53,17.79 v2(43.71,17.97)
R_EMAC[1]_TXD0: length 15.6
  TOP w0.114: U19.19 49.29,17.52 v2(49.27,17.54)
  INT_L3 w0.091: v2(49.27,17.54) 49.55,17.26 50.67,17.26 50.77,17.17 50.77,17.02 50.67,16.93 49.24,16.93 49.09,17.08 48.56,17.08 48.23,17.41 44.42,17.41 44.23,17.6 44.23,18.05 43.96,18.33 43.38,18.33 43.3,18.25 43.3,18.09 43.22,18.01 43.11,18.01 43.03,18.09 43.03,18.25 42.95,18.33 42.33,18.33 42.23,18.43 v3(42.23,18.66)
  SIG_L10 w0.091: v5(40.15,18.86) 40.48,19.19 41.93,19.19 42.23,18.89 v3(42.23,18.66)
  BOTTOM w0.114: R295.2 40.1,18.81 v5(40.15,18.86)
R_EMAC[1]_TXD1: length 15
  TOP w0.114: v2(42.21,16.9) 42.35,16.76 43.43,16.76 43.72,17.04 R298.2 ; v2(49.69,16.6) U19.18
  INT_L3 w0.091: v2(42.21,16.9) 42.21,16.8 42.64,16.37 42.83,16.37 42.91,16.29 42.91,15.93 42.99,15.85 43.11,15.85 43.19,15.93 43.19,16.29 43.27,16.37 43.38,16.37 43.46,16.29 43.46,15.93 43.54,15.85 43.66,15.85 43.74,15.93 43.74,16.29 43.82,16.37 43.93,16.37 44.01,16.29 44.01,15.13 44.09,15.05 44.2,15.05 44.28,15.13 44.28,16.29 44.36,16.37 44.48,16.37 44.56,16.29 44.56,15.93 44.64,15.85 44.75,15.85 44.83,15.93 44.83,16.29 44.91,16.37 49.46,16.37 v2(49.69,16.6)
R_EMAC[1]_TXD2: length 17
  TOP w0.114: U19.17 50.09,18.37 v2(49.95,18.5)
  INT_L3 w0.091: v2(49.95,18.5) 49.78,18.33 49.26,18.33 48.6,18.99 47.78,18.99 47.7,19.07 47.7,19.9 47.62,19.98 47.51,19.98 47.43,19.9 47.43,19.07 47.35,18.99 47.23,18.99 47.15,19.07 47.15,19.9 47.07,19.98 46.96,19.98 46.88,19.9 46.88,19.07 46.8,18.99 46.25,18.99 45.89,19.34 43.17,19.34 42.92,19.09 v3(42.92,18.91)
  SIG_L10 w0.091: v3(42.92,18.91) 42.38,19.44 40.25,19.44 v5(39.74,19.95)
  BOTTOM w0.114: R299.2 39.71,19.92 v5(39.74,19.95)
R_EMAC[1]_TXD3: length 14.1
  TOP w0.114: U19.16 v2(50.49,17.59)
  INT_L3 w0.091: v2(50.49,17.59) 50.49,17.87 50.39,17.97 50.06,17.97 49.98,17.89 49.98,17.64 49.9,17.56 49.79,17.56 49.71,17.64 49.71,17.89 49.63,17.97 49.27,17.97 49.04,17.74 48.65,17.74 48.57,17.82 48.57,17.99 48.49,18.07 48.38,18.07 48.3,17.99 48.3,17.82 48.21,17.74 47.98,17.74 47.9,17.82 47.9,18.09 47.82,18.17 47.71,18.17 47.63,18.09 47.63,17.82 47.55,17.74 47.44,17.74 47.35,17.82 47.35,18.09 47.27,18.17 47.16,18.17 47.08,18.09 47.08,17.82 47,17.74 46.89,17.74 46.81,17.82 46.81,18.09 46.73,18.17 46.61,18.17 46.53,18.09 46.53,17.82 46.45,17.74 46.34,17.74 46.26,17.82 46.26,18.09 46.18,18.17 46.06,18.17 45.98,18.09 45.98,17.82 45.9,17.74 45.79,17.74 45.71,17.82 45.71,18.09 45.63,18.17 45.52,18.17 45.43,18.09 45.43,17.82 45.35,17.74 45.24,17.74 45.16,17.82 45.16,18.09 45.08,18.17 44.97,18.17 44.89,18.09 44.89,17.82 44.81,17.74 44.62,17.74 44.51,17.86 44.51,18.24 44.34,18.4 44.34,18.51 44.37,18.54 44.37,18.68 44.11,18.94 43.88,18.94 v2(43.68,18.73)
R_QSPI_FLASH_QSPI1_CS0: length 31.8
  INT_L3 w0.091: v3(41.15,21.08) 41.71,20.51 43.93,20.51 45.31,21.89 45.31,23.08 45.22,23.16 44.88,23.16 44.8,23.24 44.8,23.36 44.88,23.44 45.22,23.44 45.31,23.52 45.31,23.63 45.22,23.71 44.88,23.71 44.8,23.79 44.8,23.91 44.88,23.99 45.22,23.99 45.31,24.07 45.31,24.18 45.22,24.26 44.88,24.26 44.8,24.34 44.8,24.45 44.88,24.54 45.22,24.54 45.31,24.62 45.31,24.73 45.22,24.81 44.88,24.81 44.8,24.89 44.8,25 44.88,25.08 45.22,25.08 45.31,25.16 45.31,25.28 45.22,25.36 44.88,25.36 44.8,25.44 44.8,25.55 44.88,25.63 45.22,25.63 45.31,25.71 45.31,25.83 45.22,25.91 44.88,25.91 44.8,25.99 44.8,26.1 44.88,26.18 45.16,26.18 45.26,26.27 45.26,26.4 44.9,26.76 44.9,27.9 44.67,28.13 44.67,28.56 45.15,29.05 45.15,30 45.06,30.09 44.77,30.09 44.67,29.99 44.67,29.02 44.21,28.56 44.21,27.93 v2(44.29,27.85)
  SIG_L10 w0.091: v5(41.67,20.74) 41.34,21.08 v3(41.15,21.08)
  BOTTOM w0.114: U15.1 40.55,12.87 40.33,13.09 40.33,16.4 40.07,16.65 40.07,17.63 40.77,18.33 40.77,19.2 41.04,19.47 41.04,19.61 40.95,19.7 40.95,19.84 41.06,19.94 41.2,19.94 41.28,19.86 41.43,19.86 41.67,20.1 v5(41.67,20.74)
R_QSPI_FLASH_QSPI1_D0: length 32.3
  INT_L3 w0.091: v3(43.02,22.01) 43.02,22.21 44.06,23.25 44.06,25.84 43.48,26.43 43.48,28.87 43.56,28.95 43.78,28.95 43.86,29.03 43.86,29.14 43.78,29.22 43.56,29.22 43.48,29.3 43.48,29.42 43.56,29.5 43.78,29.5 43.86,29.58 43.86,29.69 43.78,29.77 43.56,29.77 43.48,29.85 43.48,29.97 43.56,30.05 43.78,30.05 43.86,30.13 43.86,30.24 43.78,30.32 43.56,30.32 43.48,30.4 43.48,30.87 43.76,31.15 v2(44.39,31.15)
  SIG_L10 w0.091: v5(42.89,21.22) 43.02,21.35 v3(43.02,22.01)
  BOTTOM w0.114: U15.5 44.36,5.78 44.16,5.98 44.16,10.3 44.96,11.09 44.96,13.75 43.81,14.9 43.25,14.9 42.31,15.84 42.31,19.06 42.94,19.7 42.94,21.17 v5(42.89,21.22)
R_QSPI_FLASH_QSPI1_D1: length 32.1
  INT_L3 w0.091: v2(44.4,26.88) 44.58,26.88 44.67,26.97 44.67,27.47 44.59,27.55 44.11,27.55 44.01,27.45 44.01,26.68 44.57,26.12 44.57,22.7 45.03,22.24 45.03,21.98 43.81,20.76 43.44,20.76 43.36,20.85 43.36,21.01 43.28,21.1 43.17,21.1 43.09,21.01 43.09,20.85 43,20.76 42.89,20.76 42.81,20.85 42.81,21.01 42.73,21.1 42.62,21.1 42.54,21.01 42.54,20.85 42.46,20.76 41.83,20.76 41.55,21.04 41.55,21.24 41.31,21.48 40.72,21.48 40.63,21.57 40.63,21.82 40.72,21.91 41.44,21.91 41.95,21.39 v3(41.97,21.39)
  SIG_L10 w0.091: v5(42.16,20.18) 42.08,20.26 42.08,21.15 42.03,21.2 42.03,21.22 41.96,21.29 41.96,21.38 v3(41.97,21.39)
  BOTTOM w0.114: U15.2 41.82,12.76 41.52,13.07 41.29,13.07 41.29,13.06 41.05,13.06 40.58,13.53 40.58,14.35 40.68,14.45 41.57,14.45 41.67,14.55 41.67,14.69 41.57,14.79 40.68,14.79 40.58,14.89 40.58,15.04 40.68,15.14 41.57,15.14 41.67,15.24 41.67,15.38 41.57,15.48 40.68,15.48 40.58,15.58 40.58,15.72 40.68,15.82 41.57,15.82 41.67,15.92 41.67,16.07 41.57,16.17 40.68,16.17 40.58,16.27 40.58,16.47 41.07,16.96 41.07,18.97 42.16,20.05 v5(42.16,20.18)
R_QSPI_FLASH_QSPI1_D2: length 32.3
  INT_L3 w0.091: v2(44.31,31.92) 43.96,31.92 43.88,31.84 43.88,31.64 43.8,31.56 43.68,31.56 43.6,31.64 43.6,31.84 43.52,31.92 43.41,31.92 43.33,31.84 43.33,31.64 43.25,31.56 43.13,31.56 43.05,31.64 43.05,31.84 42.97,31.92 42.79,31.92 42.59,31.71 42.59,31.08 42.67,31 43.07,31 43.15,30.92 43.15,30.81 43.07,30.73 42.67,30.73 42.59,30.65 42.59,30.53 42.67,30.45 43.07,30.45 43.15,30.37 43.15,30.26 43.07,30.18 42.67,30.18 42.59,30.1 42.59,29.99 42.67,29.9 43.07,29.9 43.15,29.82 43.15,29.71 43.07,29.63 42.67,29.63 42.59,29.55 42.59,29.44 42.67,29.36 43.07,29.36 43.15,29.28 43.15,29.16 43.07,29.08 42.67,29.08 42.59,29 42.59,28.89 42.67,28.81 43.07,28.81 43.15,28.73 43.15,28.61 43.07,28.53 42.67,28.53 42.59,28.45 42.59,28.34 42.67,28.26 43.07,28.26 43.15,28.18 43.15,26.33 43.81,25.67 43.81,25.05 43.73,24.97 43.23,24.97 43.15,24.89 43.15,24.78 43.23,24.7 43.73,24.7 43.81,24.62 43.81,24.51 43.73,24.42 43.23,24.42 43.15,24.34 43.15,24.23 43.23,24.15 43.73,24.15 43.81,24.07 43.81,23.48 42.54,22.21 v3(42.54,21.58)
  SIG_L10 w0.091: v3(42.54,21.58) 42.54,21.02 v5(42.59,20.97)
  BOTTOM w0.114: R193.1 43.02,14.62 42.05,15.58 42.05,19.29 42.59,19.82 v5(42.59,20.97) ; R193.1 43.09,13.75 U15.3 ; R193.1 43.02,13.82 R189.1
R_QSPI_FLASH_QSPI1_D3: length 39.6
  INT_L3 w0.091: v2(44.31,30.44) 44.31,29.05 43.73,28.46 43.73,26.61 44.31,26.02 44.31,23.08 43.6,22.37 43.6,21.7 v3(43.43,21.53)
  SIG_L10 w0.091: v3(43.43,21.53) 43.51,21.44 v5(43.51,21.05)
  BOTTOM w0.114: 39.12,6.52 R195.1 ; 39.12,6.52 40.14,6.52 41.82,4.84 U15.7 41.82,3.49 42.24,3.08 44.92,3.08 45.2,3.36 45.2,5.69 44.49,6.39 44.49,10.12 45.2,10.83 45.2,13.89 43.82,15.27 43.34,15.27 42.55,16.06 42.55,18.85 43.3,19.6 43.3,20.84 v5(43.51,21.05) ; 39.12,6.52 R192.1
R_QSPI_FLASH_QSPI1_SCLK: length 7.1
  BOTTOM w0.114: U15.6 43.09,6.24 40.4,8.93 R186.2
RSTOUTN: length 92.9
  TOP w0.12: v8(23.07,21.57) U6.F23
  INT_L3 w0.091: v2(27.04,9.41) v3(26.7,9.75)
  SIG_L5 w0.091: v3(21.28,16.88) 21.51,16.65 23.62,16.65 24.18,16.09 26.55,16.09 27.09,16.63 27.09,17.49 27.35,17.74 31.6,22 32.02,22 32.29,22.27 32.29,23.33 32.51,23.55 32.78,23.55 33.04,23.82 33.04,24.13 32.78,24.39 32.78,24.75 32.29,25.24 32.29,31.33 32.51,31.55 32.52,31.55 32.73,31.76 32.73,32.3 33.09,32.66 33.09,32.93 33.31,33.15 33.58,33.15 33.84,33.41 33.84,35.8 33.89,35.84 33.89,36.94 34.15,37.21 34.15,40.45 33.55,41.06 v3(33.55,41.11)
  SIG_L10 w0.091: v5(37.25,4.36) 37.25,4.13 36.87,3.75 33.33,3.75 30.76,6.31 29.68,6.31 27.35,8.65 27.35,9.51 v5(27.27,9.59) 27.25,9.59 27.12,9.72 26.74,9.72 v3(26.7,9.75) 26.7,10.21 25.95,10.96 21.28,10.96 20.82,11.42 20.82,14.9 21.32,15.4 21.32,16.37 v5(21.33,16.37) 21.33,16.83 v3(21.28,16.88) ; v5(38.07,8.29) 38,8.29 37.12,9.18 v3(36.47,9.18) ; v3(33.55,41.11) 33.55,41.24 35.45,43.14 35.45,48.25 v5(41.19,53.99)
  BOTTOM w0.114: v5(21.33,16.37) 21.3,16.35 20.61,16.35 20.55,16.41 ; v5(41.19,53.99) 41.19,54.03 R25.1 ; v5(37.25,4.36) 37.25,4.75 38.15,5.64 ; 38.15,5.64 R51.1 ; 38.15,5.64 38.15,5.65 37.71,6.08 37.71,6.88 R192.2 38.17,7.35 R52.1 38.07,8.26 v5(38.07,8.29) ; 20.55,16.41 R321.1 ; 20.55,16.41 21.05,16.9 21.3,16.9 21.87,17.48 21.87,19.01 21.87,19.01 21.87,19.76 22.67,20.56 22.67,20.94 23.07,21.34 v8(23.07,21.57)
RTC_CLKOE: length 9.1
  TOP w0.12: v2(31.46,17.39) 31.68,17.39 U6.A12
  INT_L3 w0.091: v2(31.46,17.39) 31.44,17.36 v3(31.44,16.6)
  SIG_L10 w0.091: v3(31.44,16.6) 31.49,16.55 31.49,16.12 v5(31.49,16.12)
  BOTTOM w0.114: U13.1 33.17,12.14 R153.1 32.45,12.28 R157.1 32.02,12.28 31.51,12.79 31.51,16.04 31.49,16.06 v5(31.49,16.12)
RTC_CLKOUT_1V8: length 75.3
  TOP w0.114: v2(34.26,14.92) 34.39,14.79 34.39,5.83 34.04,5.49 34.04,4.17 v2(34.15,4.05) 34.82,3.39 R163.1
  INT_L3 w0.091: v3(35.07,18.35) 35.07,17.79 35.33,17.53 35.33,17.53 35.42,17.43 35.42,17.18 35.84,16.77 35.84,15.89 34.87,14.92 v2(34.26,14.92) ; v2(34.15,4.05) 34.36,4.25 34.47,4.25 34.51,4.29 v3(34.57,4.29)
  SIG_L5 w0.091: v3(35.07,18.35) 35.07,18.61 34.69,18.98 34.69,21.73 34.91,21.95 35.36,21.95 35.49,22.08 35.49,22.66 36.24,23.41 36.24,24.7 36.88,25.34 36.88,25.76 36.8,25.85 36.8,27.84 36.7,27.93 36.45,27.93 36.02,28.35 35.76,28.35 34.7,29.41 34.7,29.72 34.92,29.94 34.92,30.79 34.69,31.02 34.69,32.53 35.51,33.35 35.51,34.88 35.42,34.97 35.42,37.27 34.44,38.25 34.44,38.58 34.76,38.91 34.76,41.39 34.18,41.97 33.16,41.97 32.45,41.26 32.45,41.01 v3(32.58,40.88)
  SIG_L10 w0.091: v5(31.59,42.41) 31.59,41.72 32.41,40.89 32.57,40.89 ; v5(42.77,59.92) 43.81,58.87 43.81,56.91 41.67,54.78 40.94,54.78 40.49,54.33 40.49,53.72 34.92,48.15 34.92,43.32 32.57,40.97 32.57,40.89 ; 32.57,40.89 v3(32.58,40.88)
  BOTTOM w0.114: R18.1 v5(42.77,59.92)
RTC_CLKOUT_3V3: length 7.5
  TOP w0.114: U14.3 35.94,7.7 34.89,8.75 v2(34.89,13.27)
  INT_L3 w0.091: v3(35.09,12.81) 34.89,13.02 v2(34.89,13.27)
  SIG_L10 w0.091: v5(35.09,13.3) 35.09,13.3 v3(35.09,12.81)
  BOTTOM w0.114: v5(35.09,13.3) 35.08,13.3 R165.2
RTC_CLKOUT_3V3_R: length 1.4
  BOTTOM w0.114: U13.3 34.77,12.04 R165.1
RTC_INT: length 39.7
  INT_L3 w0.091: v2(29.05,35.57) 28.13,35.57 v3(27.96,35.4)
  SIG_L8 w0.091: v3(33.21,9.64) 33.23,9.66 33.23,12.61 35.84,15.22 35.84,16.77 35.81,16.8 35.81,16.8 34.64,17.97 34.64,18.09 34.22,18.5 33.6,18.5 33.06,19.04 33.06,29.71 32.82,29.95 32.79,29.95 32.78,29.96 32.53,29.96 32.25,30.24 32.25,32.22 32,32.47 32,32.75 31.23,33.52 31.22,33.52 31.17,33.57 31.05,33.57 30.14,34.48 28.64,34.48 27.96,35.17 v3(27.96,35.4)
  SIG_L10 w0.091: v5(33.62,9.39) 33.47,9.39 33.22,9.64 v3(33.21,9.64)
  BOTTOM w0.114: R164.2 35.57,7.96 U13.7 35.57,8.73 ; v5(33.62,9.39) 33.65,9.41 35.25,9.41 35.57,9.08 35.57,8.73 ; R61.1 36.67,9.82 35.57,8.73
RTCK: length 1.8
  TOP w0.114: R169.2 13.82,3.19 P1.9
RTCKR: length 26.2
  TOP w0.114: U6.E18 v2(27.09,20.79)
  INT_L3 w0.091: v2(13.94,4.43) 14.52,3.85 18.46,3.85 23.14,8.53 23.14,10.29 25.99,13.14 27.3,14.45 27.3,16.93 27.14,17.08 27.14,17.67 27.44,17.97 27.44,20.39 27.09,20.74 v2(27.09,20.79)
SATA1_RX0_N: length 5.2
  TOP w0.102: U6.AH9 34.73,39.57 34.84,39.68 34.84,39.94 34.94,40.05 34.94,40.22 35.07,40.35 35.25,40.35 35.38,40.48 35.38,40.65 35.5,40.78 35.68,40.78 35.81,40.91 35.81,41.09 35.94,41.21 36.11,41.21 36.24,41.34 36.24,41.52 36.37,41.65 36.54,41.65 36.61,41.72 38,41.72 C171.2
SATA1_RX0_P: length 5.2
  TOP w0.102: U6.AG9 35.09,39.2 35.09,39.84 36.72,41.47 38.05,41.47 C173.2
SATA1_TX0_N: length 2.9
  TOP w0.102: U6.AG10 33.87,38.87 34.28,39.28 34.28,40.29 34.61,40.62 34.61,40.83 34.61,41.03 34.87,41.29 C167.2
SATA1_TX0_P: length 2.2
  TOP w0.102: U6.AH10 34.03,39.73 34.03,39.94 33.88,40.09 33.88,40.24 34.36,40.72 34.36,41.01 34.07,41.3 C170.2
SMPS1_SW: length 3.5
  TOP w0.114: U3.E11 U3.E12 U3.E13 32.34,49.94 33.06,49.21 v7(33.24,49.21)
  vias: v7(32.58,49.16)
SMPS2_SW: length 6.1
  TOP w0.114: U3.F11 U3.F12 U3.F13 31.54,47.92 32.5,46.95 L2.1
SMPS3_SW: length 5.9
  TOP w0.114: L3.1 29.14,46.99 U3.J13 U3.J12 U3.J11
SMPS4_SW: length 5.9
  TOP w0.114: L4.1 30.74,64.13 U3.G1 U3.G2 U3.G3
SMPS5_SW: length 1.6
  TOP w0.114: U3.H1 U3.H2 U3.H3
  vias: v7(29.81,61.55) v7(29.9,60.81)
SMPS6_SW: length 9
  TOP w0.114: U3.M5 U3.N5 25.38,57.02 22.47,59.93 20.08,59.93 L6.1
SMPS7_SW: length 5.9
  TOP w0.114: U3.D3 U3.D2 U3.D1 33.14,63.86 L7.1
SMPS8_SW: length 5
  TOP w0.114: L8.1 23.37,53.02 U3.N10 U3.M10
SMPS9_SW: length 5.2
  TOP w0.114: L9.1 23.7,55.42 U3.N7 U3.M7
SODIMM__CLKOUT2/GPIO6_17: length 4.9
  TOP w0.12: v8(27.07,19.97) U6.D18
  BOTTOM w0.12: v8(27.07,19.97) 27.47,19.57 27.47,18.44 26.72,17.7 R209.1
SODIMM__GPIO6_19: length 2.9
  TOP w0.114: R173.1 21.02,16.67 21.45,17.1 21.45,18.39 U6.B26
SODIMM__SPI1_CS0: length 2
  TOP w0.114: U6.A24 22.67,17.03 R258.1
SODIMM__SPI1_D0: length 2.8
  TOP w0.114: U6.B25 22.28,18.36 22.28,16.59 R255.1
SODIMM__SPI1_D1: length 6.6
  TOP w0.114: v8(28.67,21.57) U6.F16
  BOTTOM w0.114: v8(28.67,21.57) 28.67,21.33 29.61,20.4 29.61,16.52 R254.1
SODIMM__SPI1_SCLK: length 1.7
  TOP w0.114: U6.A25 21.8,17.91 R253.1
SODIMM__UART1_RXD: length 2.8
  TOP w0.114: 19.87,18.37 19.87,16.69 R250.1
  TOP w0.12: 19.87,18.37 U6.B27
SODIMM__UART1_TXD: length 2.3
  TOP w0.12: v8(21.47,19.98) U6.C26
  BOTTOM w0.114: v8(21.47,19.98) 20.89,19.4 R251.1
SODIMM__UART2_RXD: length 4.5
  TOP w0.114: R256.1 18.61,16.31 18.61,18.7
  TOP w0.12: 18.61,18.7 18.61,19.37 19.47,20.23 U6.D28
SODIMM__UART2_TXD: length 4.5
  TOP w0.12: R257.1 20.67,16.67 20.67,19.97 U6.D26
SODIMM__UART3_RXD: length 3.6
  TOP w0.114: R240.1 42.71,32.75 41.93,31.97 40.66,31.97 U6.V2
SODIMM__UART3_TXD: length 3.2
  TOP w0.114: 41.16,33.17 42.58,33.17 42.96,33.56 42.96,34.15 43.36,34.54 R241.1
  TOP w0.12: 41.16,33.17 U6.Y1
SODIMM__UART5_RXD: length 3.1
  TOP w0.114: R213.1 27.18,16.27 26.25,17.2 26.25,18.29 26.67,18.71 U6.B19
SODIMM__UART5_TXD: length 3.7
  TOP w0.12: v8(27.87,19.17) U6.C17
  BOTTOM w0.12: v8(27.87,19.17) 27.87,17.75 27.56,17.44 R215.1
SODIMM__UART6_RXD: length 5.4
  TOP w0.12: v8(32.67,22.37) U6.G12
  SIG_L10 w0.091: v5(34.43,20) 34.69,20.26 34.69,20.93 34.45,21.17 33.98,21.17 33.85,21.3 33.85,21.81 33.71,21.95 33.3,21.95 32.88,22.37 32.68,22.37 v8(32.67,22.37)
  BOTTOM w0.114: v5(34.43,20) 34.43,19.36 R243.1
SODIMM__UART6_TXD: length 1.8
  TOP w0.12: U6.F12 32.63,21.61 32.63,21.55 v8(32.66,21.53)
  BOTTOM w0.114: v8(32.66,21.53) 32.66,20.33 R242.1
SODIMM__UART7_RXD/GPIO5_13: length 3.1
  TOP w0.114: R211.1 27.08,17.16 27.08,18.38 27.47,18.77 U6.B18
SODIMM__UART7_TXD/GPIO5_14: length 6.6
  TOP w0.114: v8(29.47,21.57) U6.F15
  BOTTOM w0.114: v8(29.47,21.57) 29.47,21.4 30.19,20.67 30.19,16.77 R210.1
SODIMM__UART8_RXD: length 11
  TOP w0.114: v8(25.47,22.37) 25.78,22.69
  TOP w0.12: 25.78,22.69 U6.G20
  BOTTOM w0.114: v8(25.47,22.37) 25.47,22.4 25.85,22.78 26.5,22.78 26.71,22.57 26.71,22.15 26.89,21.97 28.83,21.97 29.07,21.74 29.07,21.41 29.88,20.59 29.88,16.26 R249.1
SODIMM__UART8_TXD: length 8.1
  TOP w0.12: v8(26.27,22.37) U6.G19
  BOTTOM w0.114: v8(26.27,22.37) 26.27,22.2 27.3,21.17 28.03,21.17 28.27,20.94 28.27,20.94 28.27,20.93 28.27,16.25 R248.1
SODIMM__UART10_RXD: length 6
  TOP w0.114: R174.1 25.34,16.5 24.53,17.31 v2(24.3,17.31) ; U6.E21 v2(24.72,20.83)
  INT_L3 w0.091: v2(24.3,17.31) 24.3,17.41 24.1,17.62 24.1,18.58 24.27,18.75 24.27,20.38 v2(24.72,20.83)
SODIMM__UART10_TXD: length 6.5
  TOP w0.114: U6.F20 v2(25.45,21.59)
  INT_L3 w0.091: v2(25.45,21.59) 25.82,21.22 25.82,19.78 26.18,19.42 26.18,19.35 26.44,19.09 26.44,18.27 26.04,17.88 26.04,16.8 26.07,16.77 26.07,16.76 26.25,16.57 v2(26.25,16.32)
SODIMM_ALT_BOOT: length 9.9
  TOP w0.114: XP1.185 57.22,59.78 v2(57.19,59.75)
  INT_L3 w0.091: v3(54.58,57.82) 55.64,58.89 56.33,58.89 v2(57.19,59.75)
  SIG_L10 w0.091: v5(54.14,57.59) 54.37,57.59 54.58,57.8 v3(54.58,57.82)
  BOTTOM w0.114: v5(54.14,57.59) 53.75,57.2 R326.1 53.62,56.99 Q7.G 53.52,56.23 52.8,56.96 52.06,56.96 Q8.G
SODIMM_BACKUP_BAT: length 82.5
  TOP w0.114: R319.2 55.52,60.82 TP27.1
  INT_L3 w0.091: v3(56.94,61.3) 56.91,61.28 56.35,61.28 v2(55.97,60.9)
  SIG_L5 w0.091: v3(33.71,5.23) 33.87,5.07 36.64,5.07 36.93,4.78 37.87,4.78 38.16,5.07 43.57,5.07 44.69,6.2 44.69,6.71 45.9,7.91 48.03,7.91 55.3,15.18 55.3,21.48 54.7,22.08 54.7,27.08 58.51,30.89 58.51,58.79 56.94,60.36 v3(56.94,61.3)
  SIG_L10 w0.091: v5(33.37,5.58) v3(33.71,5.23)
  BOTTOM w0.114: U13.9 33.97,7.47 R159.1 ; R168.1 R159.1 ; R159.1 33.63,7.24 33.24,6.85 33.24,5.7 v5(33.37,5.58)
SODIMM_CLKOUT2/GPIO6_17: length 76.3
  SIG_L5 w0.091: v3(43.53,5.6) 43.53,5.85 45.97,8.29 47.74,8.29 54.75,15.31 54.75,21.72 53.16,23.31 53.16,29.01 54.31,30.16 54.79,30.16 58.11,33.48 v3(58.11,49.16)
  SIG_L10 w0.091: v3(43.53,5.6) 43.17,5.96 36.36,5.96 36.13,6.19 32.42,6.19 32.36,6.25 32.26,6.25 26.71,11.79 26.71,14.77 26.48,15 v5(26.43,15) ; v5(58.11,49.58) v3(58.11,49.16)
  BOTTOM w0.114: XP1.152 v5(58.11,49.58) ; v5(26.43,15) 26.6,15.17 R209.2
SODIMM_COLD_RESET_IN: length 17.2
  TOP w0.114: U1.3 47.2,51.8 R4.1 47.53,52.19 46.83,52.9 v2(46.83,53.05)
  GND_L2 w0.091: v2(57.62,55.61) v1(58.01,55.61)
  INT_L3 w0.091: v2(46.83,53.05) 47.02,53.24 57.2,53.24 57.62,53.66 v2(57.62,55.61)
SODIMM_DEBUG_UART3_RXD: length 19.5
  TOP w0.114: XP1.117 56.13,39.38 55.47,40.04 53.51,40.04 v2(53.48,40.07) ; R240.2 v2(44.7,32.36)
  INT_L3 w0.091: v2(53.48,40.07) 53.48,39.13 53.23,38.88 53.23,37.28 50.76,34.81 47.87,34.81 45.99,32.93 45.58,32.93 45.01,32.36 v2(44.7,32.36)
SODIMM_DEBUG_UART3_TXD: length 18.1
  TOP w0.114: XP1.111 56.42,37.58 54.99,39 52.35,39 52.19,39 v2(52.09,38.9)
  INT_L3 w0.091: v2(44.39,34.71) 44.67,34.99 47.43,34.99 47.73,35.28 50.62,35.28 52.37,37.03 52.37,38.14 52.09,38.42 v2(52.09,38.9)
SODIMM_DEC_POWER_DOWN: length 32.2
  TOP w0.114: v2(55.8,19.93) 55.49,19.62 v2(52.9,19.62)
  TOP w0.12: v8(41.67,29.99) 41.66,29.97 U6.T1
  INT_L3 w0.091: v2(55.8,19.93) 55.57,20.15 55.57,25.88 56.04,26.35 58.08,26.35 59,27.27 v2(59,28.59) ; v2(52.9,19.62) 52.82,19.55 v3(52.82,19.14)
  SIG_L8 w0.091: v8(41.67,29.99) 41.67,29.43 47.46,23.64 47.46,22.39 49.47,20.39 50.28,20.39 51.53,19.14 v3(52.82,19.14)
SODIMM_EEPROM_WP/QSPI_FLASH_WP: length 87.6
  TOP w0.114: XP1.189 v2(58.03,60.98)
  INT_L3 w0.091: v3(40.94,11.7) 40.48,11.24 40.48,9.72 36.77,6.01 36.77,4.43 v3(36.52,4.18) ; v2(58.03,60.98) v3(58.49,60.98)
  SIG_L5 w0.091: v3(58.49,60.98) 59.03,60.45 59.03,30.79 55.13,26.9 55.13,22.27 55.73,21.66 55.73,13.33 49.88,7.48 46.08,7.48 45.13,6.52 45.13,5.87 43.83,4.57 38.28,4.57 37.88,4.18 v3(36.52,4.18)
  SIG_L10 w0.091: v5(41.17,13.35) 41.17,11.93 v3(40.94,11.7) ; v5(36.04,4.15) 36.11,4.15 36.14,4.18 v3(36.52,4.18)
  BOTTOM w0.114: R234.1 35.22,3.33 v5(36.04,4.15) ; R189.2 41.13,13.72 41.13,13.39 v5(41.17,13.35)
SODIMM_ENABLE1(PMIC): length 34.8
  TOP w0.114: v2(29.46,57.39) 29.46,57.34 U3.J5
  INT_L3 w0.091: v2(29.46,57.39) 29.25,57.19 v3(28.82,57.19)
  SIG_L10 w0.091: v3(28.82,57.19) 29.07,56.93 29.89,56.93 30.9,57.95 32.31,57.95 37.26,62.89 37.44,62.89 44.73,62.89 45.91,61.71 50.84,61.71 52.16,63.03 56.79,63.03 57.14,63.38 v5(57.17,63.38)
  BOTTOM w0.114: XP1.198 v5(57.17,63.38)
SODIMM_ETH0_LED1_LINK_ACT_100/C: length 26.4
  TOP w0.114: v2(56.3,27.11) 56.25,27.11 54.65,25.51 54.65,23.2 54.13,22.68 49.79,22.68 49.25,23.22 49.25,26.69 48.82,27.12 R273.2 47.82,28.1 47.82,29.1 48.01,29.29 U17.36
  INT_L3 w0.091: v2(56.3,27.11) 56.68,26.73 58.03,26.73 58.56,27.27 58.56,33.19 58.51,33.24 v2(58.51,33.41)
SODIMM_ETH0_LED2_LINK_ACT_1000/: length 21.1
  TOP w0.114: U17.37 49.13,27.68 R274.2 v1(49.34,27.12) ; v2(53.56,38.67) 53.59,38.7 54.83,38.7 56.55,36.98 XP1.109
  GND_L2 w0.091: v1(49.34,27.12) v2(49.34,27.12)
  INT_L3 w0.091: v2(53.56,38.67) 53.48,38.6 53.48,37.22 49.34,33.08 v2(49.34,27.12)
SODIMM_ETH0_MDI0_N: length 5.3
  TOP w0.102: v2(54.96,30.09) 54.91,30.09 54.9,30.09 U17.3 ; v2(56.27,29.94) 56.43,29.78 56.43,29.6 56.68,29.35 57.25,29.35 57.41,29.18 XP1.83
  INT_L3 w0.089: v2(56.27,29.94) 56.34,29.88 56.36,29.75 56.22,29.62 55.76,29.62 55.37,30.01 55.06,30.01 54.98,30.09 v2(54.96,30.09)
SODIMM_ETH0_MDI0_P: length 5.3
  TOP w0.102: U17.2 54.92,29.69 54.93,29.68 v2(54.96,29.68) ; v2(56.72,29.94) 56.68,29.9 56.68,29.7 56.79,29.6 57.19,29.6 57.37,29.78 XP1.85
  INT_L3 w0.089: v2(54.96,29.68) 54.98,29.68 55.07,29.76 55.27,29.76 55.66,29.38 56.32,29.38 56.61,29.66 56.61,29.83 v2(56.72,29.94)
SODIMM_ETH0_MDI1_N: length 8.7
  TOP w0.102: U17.6 54.69,31.29 54.78,31.2 55.42,31.2 55.67,30.95 55.67,28.92 56.02,28.56 v2(56.07,28.56) ; XP1.77 57.31,27.38 57.14,27.55 56.91,27.55 v2(56.86,27.5)
  INT_L3 w0.089: v2(56.86,27.5) 56.93,27.56 57.22,27.56 57.45,27.79 57.45,28.27 57.22,28.5 56.15,28.5 56.13,28.5 v2(56.07,28.56)
SODIMM_ETH0_MDI1_P: length 8.5
  TOP w0.102: v2(55.9,27.98) 55.9,28 55.85,28.05 55.85,28.38 55.41,28.81 55.41,30.85 55.31,30.95 54.73,30.95 54.67,30.89 U17.5 ; XP1.79 57.31,27.98 57.15,27.83 56.91,27.83 56.84,27.9 v2(56.81,27.9)
  INT_L3 w0.089: v2(56.81,27.9) 56.84,27.9 56.94,27.8 57.12,27.8 57.21,27.89 57.21,28.17 57.12,28.26 55.97,28.26 55.88,28.16 55.87,28.01 v2(55.9,27.98)
SODIMM_ETH0_MDI2_N: length 5.6
  TOP w0.102: v2(55.03,32.09) 55.03,32.09 U17.8 ; XP1.89 57.49,30.98 57.36,31.11 56.63,31.11 56.38,31.36 v2(56.38,31.94)
  INT_L3 w0.089: v2(56.38,31.94) 56.41,31.92 56.41,31.69 56.3,31.59 55.82,31.59 55.31,32.09 v2(55.03,32.09)
SODIMM_ETH0_MDI2_P: length 5.6
  TOP w0.102: v2(56.76,31.92) 56.68,31.84 56.68,31.81 56.63,31.76 56.63,31.47 56.74,31.37 57.28,31.37 57.49,31.58 XP1.91 ; U17.7 54.93,31.69 54.93,31.69 v2(54.96,31.69)
  INT_L3 w0.089: v2(56.76,31.92) 56.74,31.89 56.74,31.68 56.4,31.34 55.72,31.34 55.38,31.69 v2(54.96,31.69)
SODIMM_ETH0_MDI3_N: length 6.3
  TOP w0.102: XP1.101 58.45,34.76 56.13,34.76 55.64,34.28 55.64,32.93 55.72,32.85 v2(55.72,32.73)
  INT_L3 w0.089: v2(55.72,32.73) 55.69,32.76 55.69,32.98 55.42,33.25 54.63,33.25 v2(54.6,33.29)
SODIMM_ETH0_MDI3_P: length 6.3
  TOP w0.102: v2(55.34,32.73) 55.34,32.91 55.39,32.96 55.39,34.46 55.95,35.01 58.46,35.01 XP1.103
  INT_L3 w0.089: v2(54.6,32.88) 54.71,32.99 54.73,32.99 54.75,33.01 55.27,33.01 55.34,32.94 v2(55.34,32.73)
SODIMM_ETH1_LED1_LINK_ACT_100/C: length 19.8
  TOP w0.114: v2(46.8,9.06) 46.45,9.41 R302.2 46.14,9.56 46.14,11.64 46.26,11.76 U19.36
  INT_L3 w0.091: v3(52.89,7.62) 52.89,6.17 52.33,5.62 50.86,5.62 50.55,5.93 47.88,5.93 47.07,6.74 47.07,8.79 v2(46.8,9.06)
  SIG_L10 w0.091: v5(53.18,8.01) 53.18,7.91 v3(52.89,7.62)
  BOTTOM w0.114: v5(53.18,8.01) 53.35,8.18 XP1.22
